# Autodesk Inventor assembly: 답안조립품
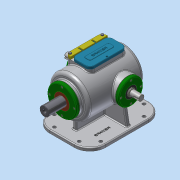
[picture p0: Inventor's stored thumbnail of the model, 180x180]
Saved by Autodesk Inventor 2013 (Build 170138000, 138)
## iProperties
Created: 2019-10
Part Number: 답안조립품
Document SubType Name: Assembly
Designer: Administrator
Mass: 7821.83 g
Surface Area: 4928.07 cm^2
Volume: 2176.15 cm^3
Density: 3.59434 g/cm^3
Author: Administrator
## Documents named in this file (17)
- C:\Users\Administrator\Desktop\391004V1019\답안조립품.iam
- C:\Users\Administrator\Desktop\391004V1019\본체.ipt
- C:\Users\Administrator\Desktop\391004V1019\가변스프링.ipt
- C:\Users\Administrator\Desktop\391004V1019\개스킷 A.ipt
- C:\Users\Administrator\Desktop\391004V1019\개스킷 B.ipt
- C:\Users\Administrator\Desktop\391004V1019\고정플레이트.ipt
- C:\Users\Administrator\Desktop\391004V1019\베어링 6205.ipt
- 베어링 6205.ipt
- C:\Users\Administrator\Desktop\391004V1019\볼트 M4x0.7.ipt
- C:\Users\Administrator\Desktop\391004V1019\부시.ipt
- C:\Users\Administrator\Desktop\391004V1019\상부커버.ipt
- C:\Users\Administrator\Desktop\391004V1019\슬라이드 커버.ipt
- C:\Users\Administrator\Desktop\391004V1019\슬라이드.ipt
- C:\Users\Administrator\Desktop\391004V1019\오일 실 25 38 8.ipt
- C:\Users\Administrator\Desktop\391004V1019\육각머리볼트 M4.ipt
- C:\Users\Administrator\Desktop\391004V1019\축 커버.ipt
- C:\Users\Administrator\Desktop\391004V1019\편심축.ipt
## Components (17 placed, 5 different names)
1. 가변스프링:1
2. 개스킷 A:1
3. 고정플레이트:1
4. 개스킷 B:1
5. 개스킷 B:2
6. M4x0.7:2
7. M4x0.7:3
8. M4x0.7:4
9. M4x0.7:5
10. M4x0.7:6
11. M4x0.7:7
12. M4x0.7:8
13. M4x0.7:9
14. M4x0.7:10
15. M4x0.7:11
16. M4x0.7:12
17. M4x0.7:13
